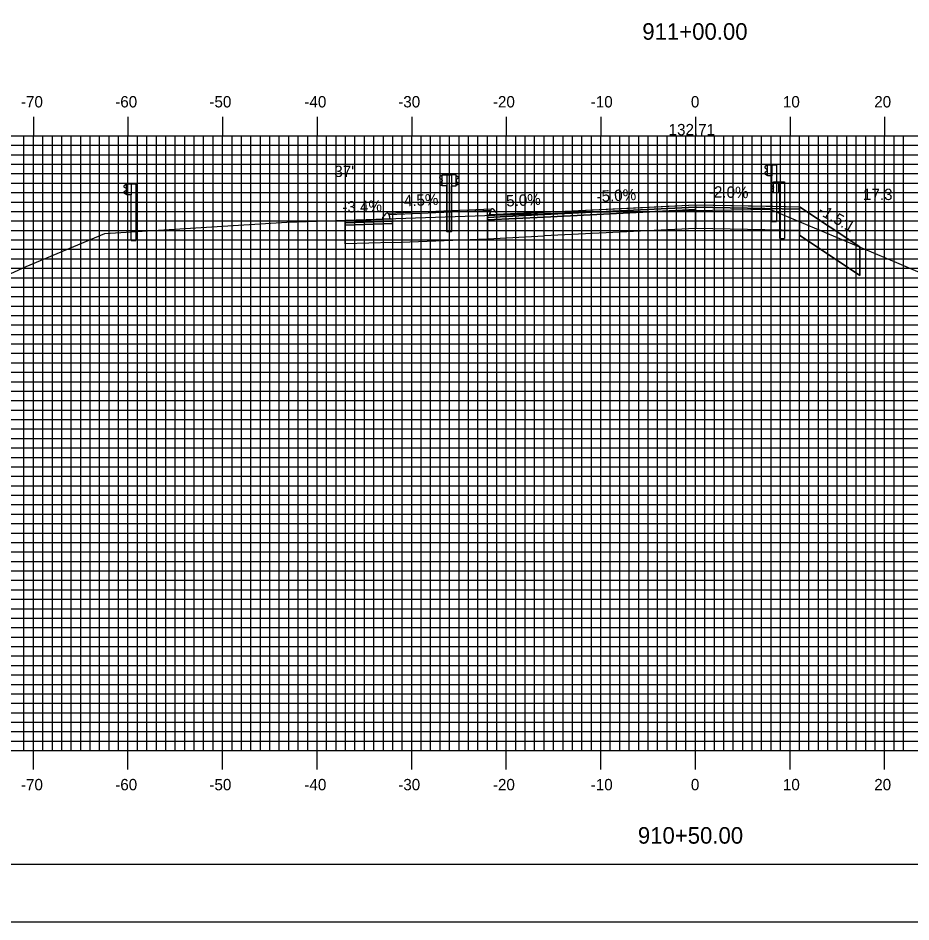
# Model space of a CAD drawing. Extents: x 859471 to 859814, y 364765 to 364985.
# Drawn here: x 859565.3 to 859659.7, y 364765.2 to 364860.7 of the extents above; entities that cross this region are included whole.
import ezdxf

# ---------------------------------------------------------------- set-up
doc = ezdxf.new("R2010")
doc.units = 0
for name, color, linetype in [('ANNOTATION', 7, 'Continuous'), ('BORDER', 7, 'Continuous'), ('D_Curb_Type_3M2_Lt', 7, 'Continuous'), ('D_Curb_Type_3M2_Rt', 7, 'Continuous'), ('D_Guardrail_Beam_Rt', 7, 'Continuous'), ('D_Roadway_Centerline', 7, 'Continuous'), ('D_Roadway_Centerline_Text', 7, 'Continuous'), ('D_Roadway_Edge_Shoulder', 7, 'Continuous'), ('D_Roadway_Edge_TW', 7, 'Continuous'), ('D_Roadway_FinishedGrade', 7, 'Continuous'), ('D_Roadway_Pavement', 7, 'Continuous'), ('D_Roadway_SlopeLines', 7, 'Continuous'), ('D_Roadway_SubGrade', 7, 'Continuous'), ('D_Text_Standard', 7, 'Continuous'), ('H_V ANNOTATION', 7, 'Continuous'), ('M_Guardrail', 7, 'Continuous'), ('M_Roadway_Centerline', 7, 'Continuous'), ('MAJOR', 7, 'Continuous'), ('MINOR', 7, 'Continuous'), ('PATTERNING', 7, 'Continuous'), ('PLOT BOUNDARY', 7, 'Continuous'), ('S_Roadway_Centerline', 7, 'Continuous')]:
    doc.layers.add(name, color=color, linetype=linetype)

msp = doc.modelspace()

# ---------------------------------------------------------------- linework, layer by layer
at = {"layer": 'BORDER'}
msp.add_lwpolyline([(859487.273, 364771.302), (859807.273, 364771.302), (859807.273, 364981.302), (859487.273, 364981.302)], close=True, dxfattribs=at)
at = {"layer": 'D_Curb_Type_3M2_Lt'}
for p, q in [((859615.231, 364840.459), (859615.123, 364839.965)), ((859615.367, 364840.588), (859615.371, 364840.588)), ((859615.873, 364840.132), (859615.518, 364840.534)), ((859615.123, 364839.965), (859615.873, 364839.965)), ((859615.873, 364839.965), (859615.873, 364840.132))]:
    msp.add_line(p, q, dxfattribs=at)
msp.add_arc((859615.393, 364840.424), 0.167, 41.38705, 167.66476, dxfattribs=at)
at = {"layer": 'D_Curb_Type_3M2_Rt'}
for p, q in [((859603.826, 364839.669), (859604.18, 364840.071)), ((859603.826, 364839.502), (859603.826, 364839.669)), ((859604.576, 364839.502), (859603.826, 364839.502)), ((859604.468, 364839.996), (859604.576, 364839.502))]:
    msp.add_line(p, q, dxfattribs=at)
msp.add_arc((859604.305, 364839.961), 0.167, 12.33524, 138.61295, dxfattribs=at)
at = {"layer": 'D_Guardrail_Beam_Rt'}
for p, q in [((859645.054, 364843.334), (859644.911, 364843.234)), ((859645.144, 364843.355), (859645.07, 364843.341)), ((859645.144, 364843.439), (859645.832, 364843.439)), ((859645.144, 364842.272), (859645.144, 364843.439)), ((859645.665, 364843.439), (859645.665, 364842.272)), ((859645.769, 364843.439), (859645.769, 364842.272)), ((859645.832, 364843.439), (859646.303, 364843.439)), ((859645.832, 364843.439), (859645.832, 364842.272)), ((859646.303, 364843.439), (859646.303, 364837.439)), ((859644.911, 364843.091), (859645.106, 364842.955)), ((859645.106, 364842.756), (859644.911, 364842.62)), ((859644.911, 364842.476), (859645.054, 364842.376)), ((859645.07, 364842.37), (859645.144, 364842.355)), ((859645.14, 364842.89), (859645.14, 364842.82)), ((859645.832, 364842.272), (859645.144, 364842.272)), ((859645.811, 364837.439), (859645.811, 364842.272)), ((859645.811, 364837.439), (859646.303, 364837.439))]:
    msp.add_line(p, q, dxfattribs=at)
for centre, major_axis, start_param, end_param in [((859645.078, 364843.3), (-0.0417, 0), 4.907132, 5.323254), ((859644.961, 364843.162), (-0.0877, 0), 5.323254, 7.243116), ((859644.961, 364842.548), (-0.0877, 0), 5.323254, 7.243116), ((859645.078, 364842.41), (-0.0417, 0), 0.959931, 1.376053), ((859645.061, 364842.89), (0.0789, 0), 0, 0.959931), ((859645.061, 364842.82), (0.0789, 0), 5.323254, 6.283185)]:
    msp.add_ellipse(centre, major_axis=major_axis, ratio=0.995501, start_param=start_param, end_param=end_param, dxfattribs=at)
at = {"layer": 'D_Roadway_Centerline'}
for points in [[(859615.873, 364839.965), (859616.703, 364840.007), (859620.87, 364840.215), (859620.873, 364840.215), (859620.881, 364840.216), (859631.267, 364840.735), (859636.869, 364841.015), (859636.874, 364841.015), (859636.876, 364841.015), (859644.316, 364840.866), (859644.874, 364840.855), (859645.07, 364840.851), (859647.874, 364840.795), (859647.875, 364840.794), (859654.243, 364836.549)], [(859599.825, 364839.366), (859600.122, 364839.376), (859603.809, 364839.502), (859603.825, 364839.502), (859603.826, 364839.502)]]:
    msp.add_lwpolyline(points, dxfattribs=at)
at = {"layer": 'D_Roadway_Edge_Shoulder'}
for points in [[(859636.873, 364841.015), (859644.874, 364840.855), (859644.874, 364840.855), (859647.873, 364840.795), (859647.873, 364840.545), (859636.873, 364840.765)], [(859599.825, 364839.366), (859603.826, 364839.502), (859604.827, 364839.536), (859604.827, 364839.286), (859599.825, 364839.116)], [(859620.873, 364840.215), (859615.873, 364839.965), (859614.873, 364839.915), (859614.873, 364839.665), (859620.873, 364839.965)]]:
    msp.add_lwpolyline(points, close=True, dxfattribs=at)
at = {"layer": 'D_Roadway_Edge_TW'}
msp.add_lwpolyline([(859620.873, 364840.215), (859636.873, 364841.015), (859636.873, 364840.765), (859620.873, 364839.965)], close=True, dxfattribs=at)
at = {"layer": 'D_Roadway_FinishedGrade'}
msp.add_line((859647.875, 364840.794), (859647.875, 364837.794), dxfattribs=at)
for points in [[(859604.347, 364840.122), (859615.352, 364840.585)], [(859647.875, 364840.794), (859649.375, 364839.794), (859654.243, 364836.549)], [(859654.243, 364836.549), (859654.243, 364833.549), (859647.875, 364837.794)]]:
    msp.add_lwpolyline(points, dxfattribs=at)
at = {"layer": 'D_Roadway_Pavement'}
for points in [[(859620.873, 364839.965), (859636.873, 364840.765), (859636.873, 364840.515), (859620.873, 364839.715)], [(859620.873, 364839.965), (859614.873, 364839.665), (859614.873, 364839.415), (859620.873, 364839.715)], [(859599.825, 364839.116), (859604.827, 364839.286), (859604.827, 364839.036), (859599.825, 364838.866)]]:
    msp.add_lwpolyline(points, close=True, dxfattribs=at)
msp.add_lwpolyline([(859636.873, 364840.765), (859636.873, 364840.515)], dxfattribs=at)
msp.add_lwpolyline([(859636.873, 364840.765), (859636.873, 364840.515)], dxfattribs=at)
at = {"layer": 'D_Roadway_SlopeLines'}
msp.add_line((859647.873, 364840.795), (859654.243, 364836.549), dxfattribs=at)
at = {"layer": 'D_Roadway_SubGrade'}
for points in [[(859604.827, 364839.536), (859604.827, 364837.036), (859614.873, 364837.415), (859614.873, 364839.415), (859614.873, 364839.665), (859614.873, 364839.915), (859615.114, 364839.927), (859615.22, 364840.413), (859604.476, 364839.957), (859604.57, 364839.527)], [(859620.873, 364839.715), (859636.873, 364840.515), (859636.873, 364838.515), (859620.873, 364837.715)], [(859636.873, 364840.515), (859636.873, 364840.765), (859647.873, 364840.545), (859647.873, 364840.795), (859647.873, 364838.302), (859636.873, 364838.515)], [(859620.873, 364839.715), (859614.873, 364839.415), (859614.873, 364839.665), (859614.873, 364837.415), (859620.873, 364837.715)], [(859599.825, 364838.866), (859604.827, 364839.036), (859604.827, 364839.286), (859604.827, 364837.036), (859599.825, 364836.866)]]:
    msp.add_lwpolyline(points, close=True, dxfattribs=at)
at = {"layer": 'M_Guardrail'}
for p, q in [((859644.476, 364845.246), (859644.965, 364845.246)), ((859644.476, 364844.08), (859644.476, 364845.246)), ((859644.965, 364845.246), (859645.457, 364845.246)), ((859644.965, 364845.246), (859644.965, 364844.08)), ((859645.457, 364845.246), (859645.457, 364839.246)), ((859644.377, 364845.152), (859644.234, 364845.052)), ((859644.234, 364844.909), (859644.429, 364844.773)), ((859644.429, 364844.553), (859644.234, 364844.417)), ((859644.234, 364844.274), (859644.377, 364844.174)), ((859644.476, 364845.173), (859644.394, 364845.159)), ((859644.463, 364844.708), (859644.463, 364844.617)), ((859609.999, 364844.072), (859609.856, 364843.972)), ((859609.856, 364843.829), (859610.051, 364843.693)), ((859610.051, 364843.473), (859609.856, 364843.337)), ((859610.098, 364844.093), (859610.016, 364844.079)), ((859610.085, 364843.628), (859610.085, 364843.537)), ((859610.098, 364844.166), (859610.588, 364844.166)), ((859610.098, 364842.999), (859610.098, 364844.166)), ((859610.576, 364844.164), (859610.576, 364838.164)), ((859611.067, 364844.164), (859610.576, 364844.164)), ((859610.588, 364844.166), (859611.079, 364844.166)), ((859610.588, 364844.166), (859610.588, 364842.999)), ((859611.557, 364844.164), (859611.067, 364844.164)), ((859611.067, 364844.164), (859611.067, 364842.997)), ((859611.079, 364844.166), (859611.079, 364838.166)), ((859611.557, 364842.997), (859611.557, 364844.164)), ((859611.557, 364844.091), (859611.639, 364844.076)), ((859611.57, 364843.626), (859611.57, 364843.535)), ((859611.799, 364843.826), (859611.604, 364843.69)), ((859611.604, 364843.471), (859611.799, 364843.334)), ((859611.656, 364844.07), (859611.799, 364843.97)), ((859644.394, 364844.167), (859644.476, 364844.152)), ((859644.965, 364844.08), (859644.476, 364844.08)), ((859644.965, 364839.246), (859644.965, 364844.08)), ((859576.62, 364843.129), (859576.477, 364843.029)), ((859576.477, 364842.886), (859576.672, 364842.749)), ((859576.672, 364842.53), (859576.477, 364842.393)), ((859576.719, 364843.15), (859576.637, 364843.136)), ((859576.706, 364842.685), (859576.706, 364842.594)), ((859576.719, 364843.223), (859577.209, 364843.223)), ((859576.719, 364842.056), (859576.719, 364843.223)), ((859577.209, 364843.223), (859577.7, 364843.223)), ((859577.209, 364843.223), (859577.209, 364842.056)), ((859577.7, 364843.223), (859577.7, 364837.223)), ((859609.856, 364843.194), (859609.999, 364843.094)), ((859610.016, 364843.087), (859610.098, 364843.072)), ((859610.588, 364842.999), (859610.098, 364842.999)), ((859610.588, 364838.166), (859610.588, 364842.999)), ((859611.067, 364838.164), (859611.067, 364842.997)), ((859611.067, 364842.997), (859611.557, 364842.997)), ((859611.639, 364843.084), (859611.557, 364843.07)), ((859611.799, 364843.191), (859611.656, 364843.091)), ((859576.477, 364842.25), (859576.62, 364842.15)), ((859576.637, 364842.143), (859576.719, 364842.129)), ((859577.209, 364842.056), (859576.719, 364842.056)), ((859577.209, 364837.223), (859577.209, 364842.056)), ((859644.965, 364839.246), (859645.457, 364839.246)), ((859611.067, 364838.164), (859610.576, 364838.164)), ((859610.588, 364838.166), (859611.079, 364838.166)), ((859577.209, 364837.223), (859577.7, 364837.223))]:
    msp.add_line(p, q, dxfattribs=at)
for centre, major_axis, start_param, end_param in [((859644.284, 364844.98), (-0.0877, 0), 5.323254, 7.243116), ((859644.284, 364844.345), (-0.0877, 0), 5.323254, 7.243116), ((859644.401, 364845.118), (-0.0417, 0), 4.886922, 5.323254), ((859644.384, 364844.708), (0.0789, 0), 0, 0.959931), ((859644.384, 364844.617), (0.0789, 0), 5.323254, 6.283185), ((859609.906, 364843.9), (-0.0877, 0), 5.323254, 7.243116), ((859609.906, 364843.265), (-0.0877, 0), 5.323254, 7.243116), ((859610.023, 364844.038), (-0.0417, 0), 4.886922, 5.323254), ((859610.006, 364843.628), (0.0789, 0), 0, 0.959931), ((859610.006, 364843.537), (0.0789, 0), 5.323254, 6.283185), ((859611.649, 364843.626), (-0.0789, 0), 5.323254, 6.283185), ((859611.649, 364843.535), (-0.0789, 0), 6.283185, 7.243116), ((859611.632, 364844.036), (0.0417, 0), 0.959931, 1.396263), ((859611.749, 364843.898), (0.0877, 0), 5.323254, 7.243116), ((859611.749, 364843.263), (0.0877, 0), 5.323254, 7.243116), ((859644.401, 364844.208), (-0.0417, 0), 0.959931, 1.396263), ((859576.527, 364842.957), (-0.0877, 0), 5.323254, 7.243116), ((859576.527, 364842.322), (-0.0877, 0), 5.323254, 7.243116), ((859576.644, 364843.095), (-0.0417, 0), 4.886922, 5.323254), ((859576.627, 364842.685), (0.0789, 0), 0, 0.959931), ((859576.627, 364842.594), (0.0789, 0), 5.323254, 6.283185), ((859610.023, 364843.128), (-0.0417, 0), 0.959931, 1.396263), ((859611.632, 364843.125), (0.0417, 0), 4.886922, 5.323254), ((859576.644, 364842.184), (-0.0417, 0), 0.959931, 1.396263)]:
    msp.add_ellipse(centre, major_axis=major_axis, ratio=0.995501, start_param=start_param, end_param=end_param, dxfattribs=at)
at = {"layer": 'MAJOR'}
for p, q in [((859566.873, 364850.306), (859566.873, 364848.302)), ((859576.873, 364850.306), (859576.873, 364848.302)), ((859586.873, 364850.306), (859586.873, 364848.302)), ((859596.873, 364850.306), (859596.873, 364848.302)), ((859606.873, 364850.306), (859606.873, 364848.302)), ((859616.873, 364850.306), (859616.873, 364848.302)), ((859626.873, 364850.306), (859626.873, 364848.302)), ((859636.873, 364850.306), (859636.873, 364848.302)), ((859646.873, 364850.306), (859646.873, 364848.302)), ((859656.873, 364850.306), (859656.873, 364848.302)), ((859496.873, 364848.302), (859776.873, 364848.302)), ((859496.873, 364848.302), (859776.873, 364848.302)), ((859566.873, 364783.302), (859566.873, 364848.302)), ((859576.873, 364783.302), (859576.873, 364848.302)), ((859586.873, 364783.302), (859586.873, 364848.302)), ((859596.873, 364783.302), (859596.873, 364848.302)), ((859606.873, 364783.302), (859606.873, 364848.302)), ((859616.873, 364783.302), (859616.873, 364848.302)), ((859626.873, 364783.302), (859626.873, 364848.302)), ((859636.873, 364783.302), (859636.873, 364848.302)), ((859646.873, 364783.302), (859646.873, 364848.302)), ((859656.873, 364783.302), (859656.873, 364848.302)), ((859496.873, 364843.302), (859776.873, 364843.302)), ((859496.873, 364838.302), (859776.873, 364838.302)), ((859496.873, 364833.302), (859776.873, 364833.302)), ((859496.873, 364828.302), (859776.873, 364828.302)), ((859496.873, 364823.302), (859776.873, 364823.302)), ((859496.873, 364818.302), (859776.873, 364818.302)), ((859496.873, 364813.302), (859776.873, 364813.302)), ((859496.873, 364808.302), (859776.873, 364808.302)), ((859496.873, 364803.302), (859776.873, 364803.302)), ((859496.873, 364798.302), (859776.873, 364798.302)), ((859496.873, 364793.302), (859776.873, 364793.302)), ((859496.873, 364788.302), (859776.873, 364788.302)), ((859496.873, 364783.302), (859776.873, 364783.302)), ((859496.873, 364783.302), (859776.873, 364783.302)), ((859566.873, 364781.298), (859566.873, 364783.302)), ((859576.873, 364781.298), (859576.873, 364783.302)), ((859586.873, 364781.298), (859586.873, 364783.302)), ((859596.873, 364781.298), (859596.873, 364783.302)), ((859606.873, 364781.298), (859606.873, 364783.302)), ((859616.873, 364781.298), (859616.873, 364783.302)), ((859626.873, 364781.298), (859626.873, 364783.302)), ((859636.873, 364781.298), (859636.873, 364783.302)), ((859646.873, 364781.298), (859646.873, 364783.302)), ((859656.873, 364781.298), (859656.873, 364783.302))]:
    msp.add_line(p, q, dxfattribs=at)
at = {"layer": 'MINOR'}
for p, q in [((859565.873, 364783.302), (859565.873, 364848.302)), ((859567.873, 364783.302), (859567.873, 364848.302)), ((859568.873, 364783.302), (859568.873, 364848.302)), ((859569.873, 364783.302), (859569.873, 364848.302)), ((859570.873, 364783.302), (859570.873, 364848.302)), ((859571.873, 364783.302), (859571.873, 364848.302)), ((859572.873, 364783.302), (859572.873, 364848.302)), ((859573.873, 364783.302), (859573.873, 364848.302)), ((859574.873, 364783.302), (859574.873, 364848.302)), ((859575.873, 364783.302), (859575.873, 364848.302)), ((859577.873, 364783.302), (859577.873, 364848.302)), ((859578.873, 364783.302), (859578.873, 364848.302)), ((859579.873, 364783.302), (859579.873, 364848.302)), ((859580.873, 364783.302), (859580.873, 364848.302)), ((859581.873, 364783.302), (859581.873, 364848.302)), ((859582.873, 364783.302), (859582.873, 364848.302)), ((859583.873, 364783.302), (859583.873, 364848.302)), ((859584.873, 364783.302), (859584.873, 364848.302)), ((859585.873, 364783.302), (859585.873, 364848.302)), ((859587.873, 364783.302), (859587.873, 364848.302)), ((859588.873, 364783.302), (859588.873, 364848.302)), ((859589.873, 364783.302), (859589.873, 364848.302)), ((859590.873, 364783.302), (859590.873, 364848.302)), ((859591.873, 364783.302), (859591.873, 364848.302)), ((859592.873, 364783.302), (859592.873, 364848.302)), ((859593.873, 364783.302), (859593.873, 364848.302)), ((859594.873, 364783.302), (859594.873, 364848.302)), ((859595.873, 364783.302), (859595.873, 364848.302)), ((859597.873, 364783.302), (859597.873, 364848.302)), ((859598.873, 364783.302), (859598.873, 364848.302)), ((859599.873, 364783.302), (859599.873, 364848.302)), ((859600.873, 364783.302), (859600.873, 364848.302)), ((859601.873, 364783.302), (859601.873, 364848.302)), ((859602.873, 364783.302), (859602.873, 364848.302)), ((859603.873, 364783.302), (859603.873, 364848.302)), ((859604.873, 364783.302), (859604.873, 364848.302)), ((859605.873, 364783.302), (859605.873, 364848.302)), ((859607.873, 364783.302), (859607.873, 364848.302)), ((859608.873, 364783.302), (859608.873, 364848.302)), ((859609.873, 364783.302), (859609.873, 364848.302)), ((859610.873, 364783.302), (859610.873, 364848.302)), ((859611.873, 364783.302), (859611.873, 364848.302)), ((859612.873, 364783.302), (859612.873, 364848.302)), ((859613.873, 364783.302), (859613.873, 364848.302)), ((859614.873, 364783.302), (859614.873, 364848.302)), ((859615.873, 364783.302), (859615.873, 364848.302)), ((859617.873, 364783.302), (859617.873, 364848.302)), ((859618.873, 364783.302), (859618.873, 364848.302)), ((859619.873, 364783.302), (859619.873, 364848.302)), ((859620.873, 364783.302), (859620.873, 364848.302)), ((859621.873, 364783.302), (859621.873, 364848.302)), ((859622.873, 364783.302), (859622.873, 364848.302)), ((859623.873, 364783.302), (859623.873, 364848.302)), ((859624.873, 364783.302), (859624.873, 364848.302)), ((859625.873, 364783.302), (859625.873, 364848.302)), ((859627.873, 364783.302), (859627.873, 364848.302)), ((859628.873, 364783.302), (859628.873, 364848.302)), ((859629.873, 364783.302), (859629.873, 364848.302)), ((859630.873, 364783.302), (859630.873, 364848.302)), ((859631.873, 364783.302), (859631.873, 364848.302)), ((859632.873, 364783.302), (859632.873, 364848.302)), ((859633.873, 364783.302), (859633.873, 364848.302)), ((859634.873, 364783.302), (859634.873, 364848.302)), ((859635.873, 364783.302), (859635.873, 364848.302)), ((859637.873, 364783.302), (859637.873, 364848.302)), ((859638.873, 364783.302), (859638.873, 364848.302)), ((859639.873, 364783.302), (859639.873, 364848.302)), ((859640.873, 364783.302), (859640.873, 364848.302)), ((859641.873, 364783.302), (859641.873, 364848.302)), ((859642.873, 364783.302), (859642.873, 364848.302)), ((859643.873, 364783.302), (859643.873, 364848.302)), ((859644.873, 364783.302), (859644.873, 364848.302)), ((859645.873, 364783.302), (859645.873, 364848.302)), ((859647.873, 364783.302), (859647.873, 364848.302)), ((859648.873, 364783.302), (859648.873, 364848.302)), ((859649.873, 364783.302), (859649.873, 364848.302)), ((859650.873, 364783.302), (859650.873, 364848.302)), ((859651.873, 364783.302), (859651.873, 364848.302)), ((859652.873, 364783.302), (859652.873, 364848.302)), ((859653.873, 364783.302), (859653.873, 364848.302)), ((859654.873, 364783.302), (859654.873, 364848.302)), ((859655.873, 364783.302), (859655.873, 364848.302)), ((859657.873, 364783.302), (859657.873, 364848.302)), ((859658.873, 364783.302), (859658.873, 364848.302)), ((859496.873, 364847.302), (859776.873, 364847.302)), ((859496.873, 364846.302), (859776.873, 364846.302)), ((859496.873, 364845.302), (859776.873, 364845.302)), ((859496.873, 364844.302), (859776.873, 364844.302)), ((859496.873, 364842.302), (859776.873, 364842.302)), ((859496.873, 364841.302), (859776.873, 364841.302)), ((859496.873, 364840.302), (859776.873, 364840.302)), ((859496.873, 364839.302), (859776.873, 364839.302)), ((859496.873, 364837.302), (859776.873, 364837.302)), ((859496.873, 364836.302), (859776.873, 364836.302)), ((859496.873, 364835.302), (859776.873, 364835.302)), ((859496.873, 364834.302), (859776.873, 364834.302)), ((859496.873, 364832.302), (859776.873, 364832.302)), ((859496.873, 364831.302), (859776.873, 364831.302)), ((859496.873, 364830.302), (859776.873, 364830.302)), ((859496.873, 364829.302), (859776.873, 364829.302)), ((859496.873, 364827.302), (859776.873, 364827.302)), ((859496.873, 364826.302), (859776.873, 364826.302)), ((859496.873, 364825.302), (859776.873, 364825.302)), ((859496.873, 364824.302), (859776.873, 364824.302)), ((859496.873, 364822.302), (859776.873, 364822.302)), ((859496.873, 364821.302), (859776.873, 364821.302)), ((859496.873, 364820.302), (859776.873, 364820.302)), ((859496.873, 364819.302), (859776.873, 364819.302)), ((859496.873, 364817.302), (859776.873, 364817.302)), ((859496.873, 364816.302), (859776.873, 364816.302)), ((859496.873, 364815.302), (859776.873, 364815.302)), ((859496.873, 364814.302), (859776.873, 364814.302)), ((859496.873, 364812.302), (859776.873, 364812.302)), ((859496.873, 364811.302), (859776.873, 364811.302)), ((859496.873, 364810.302), (859776.873, 364810.302)), ((859496.873, 364809.302), (859776.873, 364809.302)), ((859496.873, 364807.302), (859776.873, 364807.302)), ((859496.873, 364806.302), (859776.873, 364806.302)), ((859496.873, 364805.302), (859776.873, 364805.302)), ((859496.873, 364804.302), (859776.873, 364804.302)), ((859496.873, 364802.302), (859776.873, 364802.302)), ((859496.873, 364801.302), (859776.873, 364801.302)), ((859496.873, 364800.302), (859776.873, 364800.302)), ((859496.873, 364799.302), (859776.873, 364799.302)), ((859496.873, 364797.302), (859776.873, 364797.302)), ((859496.873, 364796.302), (859776.873, 364796.302)), ((859496.873, 364795.302), (859776.873, 364795.302)), ((859496.873, 364794.302), (859776.873, 364794.302)), ((859496.873, 364792.302), (859776.873, 364792.302)), ((859496.873, 364791.302), (859776.873, 364791.302)), ((859496.873, 364790.302), (859776.873, 364790.302)), ((859496.873, 364789.302), (859776.873, 364789.302)), ((859496.873, 364787.302), (859776.873, 364787.302)), ((859496.873, 364786.302), (859776.873, 364786.302)), ((859496.873, 364785.302), (859776.873, 364785.302)), ((859496.873, 364784.302), (859776.873, 364784.302))]:
    msp.add_line(p, q, dxfattribs=at)
at = {"layer": 'PATTERNING'}
for p, q in [((859654.243, 364836.549), (859647.875, 364840.794)), ((859647.875, 364840.794), (859647.875, 364837.794))]:
    msp.add_line(p, q, dxfattribs=at)
msp.add_lwpolyline([(859647.875, 364837.794), (859654.243, 364833.549), (859654.243, 364836.549)], dxfattribs=at)
at = {"layer": 'PLOT BOUNDARY'}
msp.add_lwpolyline([(859471.086, 364765.184), (859811.086, 364765.184), (859811.086, 364985.184), (859471.086, 364985.184)], close=True, dxfattribs=at)
at = {"layer": 'S_Roadway_Centerline'}
msp.add_lwpolyline([(859496.873, 364813.975), (859500.423, 364813.806), (859507.188, 364813.561), (859522.602, 364815.323), (859529.195, 364817.264), (859536.581, 364819.874), (859552.667, 364828.184), (859557.574, 364830.597), (859566.091, 364834.481), (859574.422, 364837.987), (859585.19, 364838.631), (859593.654, 364839.158), (859615.671, 364839.903), (859625.157, 364840.217), (859630.585, 364840.301), (859644.73, 364840.544), (859658.145, 364834.91), (859667.119, 364831.057)], dxfattribs=at)

# ---------------------------------------------------------------- texts
at = {"layer": 'ANNOTATION'}
for s, rotation, p in [('-5.0%', 2.8622, (859626.445, 364841.296)), ('-2.0%', 358.85437, (859638.282, 364841.787)), ('-3.4%', 1.95099, (859599.556, 364840.158)), ('-4.5%', 2.55075, (859605.531, 364840.81)), ('-5.0%', 2.86254, (859616.357, 364840.792)), ('-1.5:1', 330.177, (859649.739, 364840.095))]:
    msp.add_text(s, height=1.2, rotation=rotation, dxfattribs=at).set_placement(p)
at = {"layer": 'D_Roadway_Centerline_Text'}
msp.add_text('132.71', height=1.2, dxfattribs=at).set_placement((859634.038, 364848.356))
at = {"layer": 'D_Text_Standard'}
for s, p in [("37'", (859598.693, 364843.946)), ("17.3'", (859654.591, 364841.508))]:
    msp.add_text(s, height=1.2, dxfattribs=at).set_placement(p)
at = {"layer": 'H_V ANNOTATION'}
for s, height, p in [('911+00.00', 1.75, (859631.256, 364858.458)), ('-70', 1.2, (859565.556, 364851.302)), ('-60', 1.2, (859575.524, 364851.302)), ('-50', 1.2, (859585.481, 364851.302)), ('-40', 1.2, (859595.524, 364851.302)), ('-30', 1.2, (859605.449, 364851.302)), ('-20', 1.2, (859615.46, 364851.302)), ('-10', 1.2, (859625.803, 364851.302)), ('0', 1.2, (859636.391, 364851.302)), ('10', 1.2, (859646.124, 364851.302)), ('20', 1.2, (859655.781, 364851.302)), ('-70', 1.2, (859565.556, 364779.102)), ('-60', 1.2, (859575.524, 364779.102)), ('-50', 1.2, (859585.481, 364779.102)), ('-40', 1.2, (859595.524, 364779.102)), ('-30', 1.2, (859605.449, 364779.102)), ('-20', 1.2, (859615.46, 364779.102)), ('-10', 1.2, (859625.803, 364779.102)), ('0', 1.2, (859636.391, 364779.102)), ('10', 1.2, (859646.124, 364779.102)), ('20', 1.2, (859655.781, 364779.102)), ('910+50.00', 1.75, (859630.787, 364773.458))]:
    msp.add_text(s, height=height, dxfattribs=at).set_placement(p)
at = {"layer": 'M_Roadway_Centerline'}
for s, p in [('C', (859625.152, 364840.217)), ('L', (859625.157, 364840.209)), ('C', (859593.648, 364839.158)), ('L', (859593.654, 364839.151))]:
    msp.add_text(s, height=0.0146, dxfattribs=at).set_placement(p)

doc.saveas('drawing.dxf')
